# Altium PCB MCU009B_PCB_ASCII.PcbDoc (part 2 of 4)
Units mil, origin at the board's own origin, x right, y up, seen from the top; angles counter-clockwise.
Board outline 2657.23 x 2215.46 mil, 10 copper layers (Top Layer, Internal-Plane 2, Mid-Layer 3, Mid-Layer 4, Internal-Plane 5, Internal-Plane 6, Mid-Layer 7, Mid-Layer 8, Internal-Plane 9, Bottom Layer), stack 60.8 mil thick; 232 components, 196 nets, 851 pads, 493 vias.
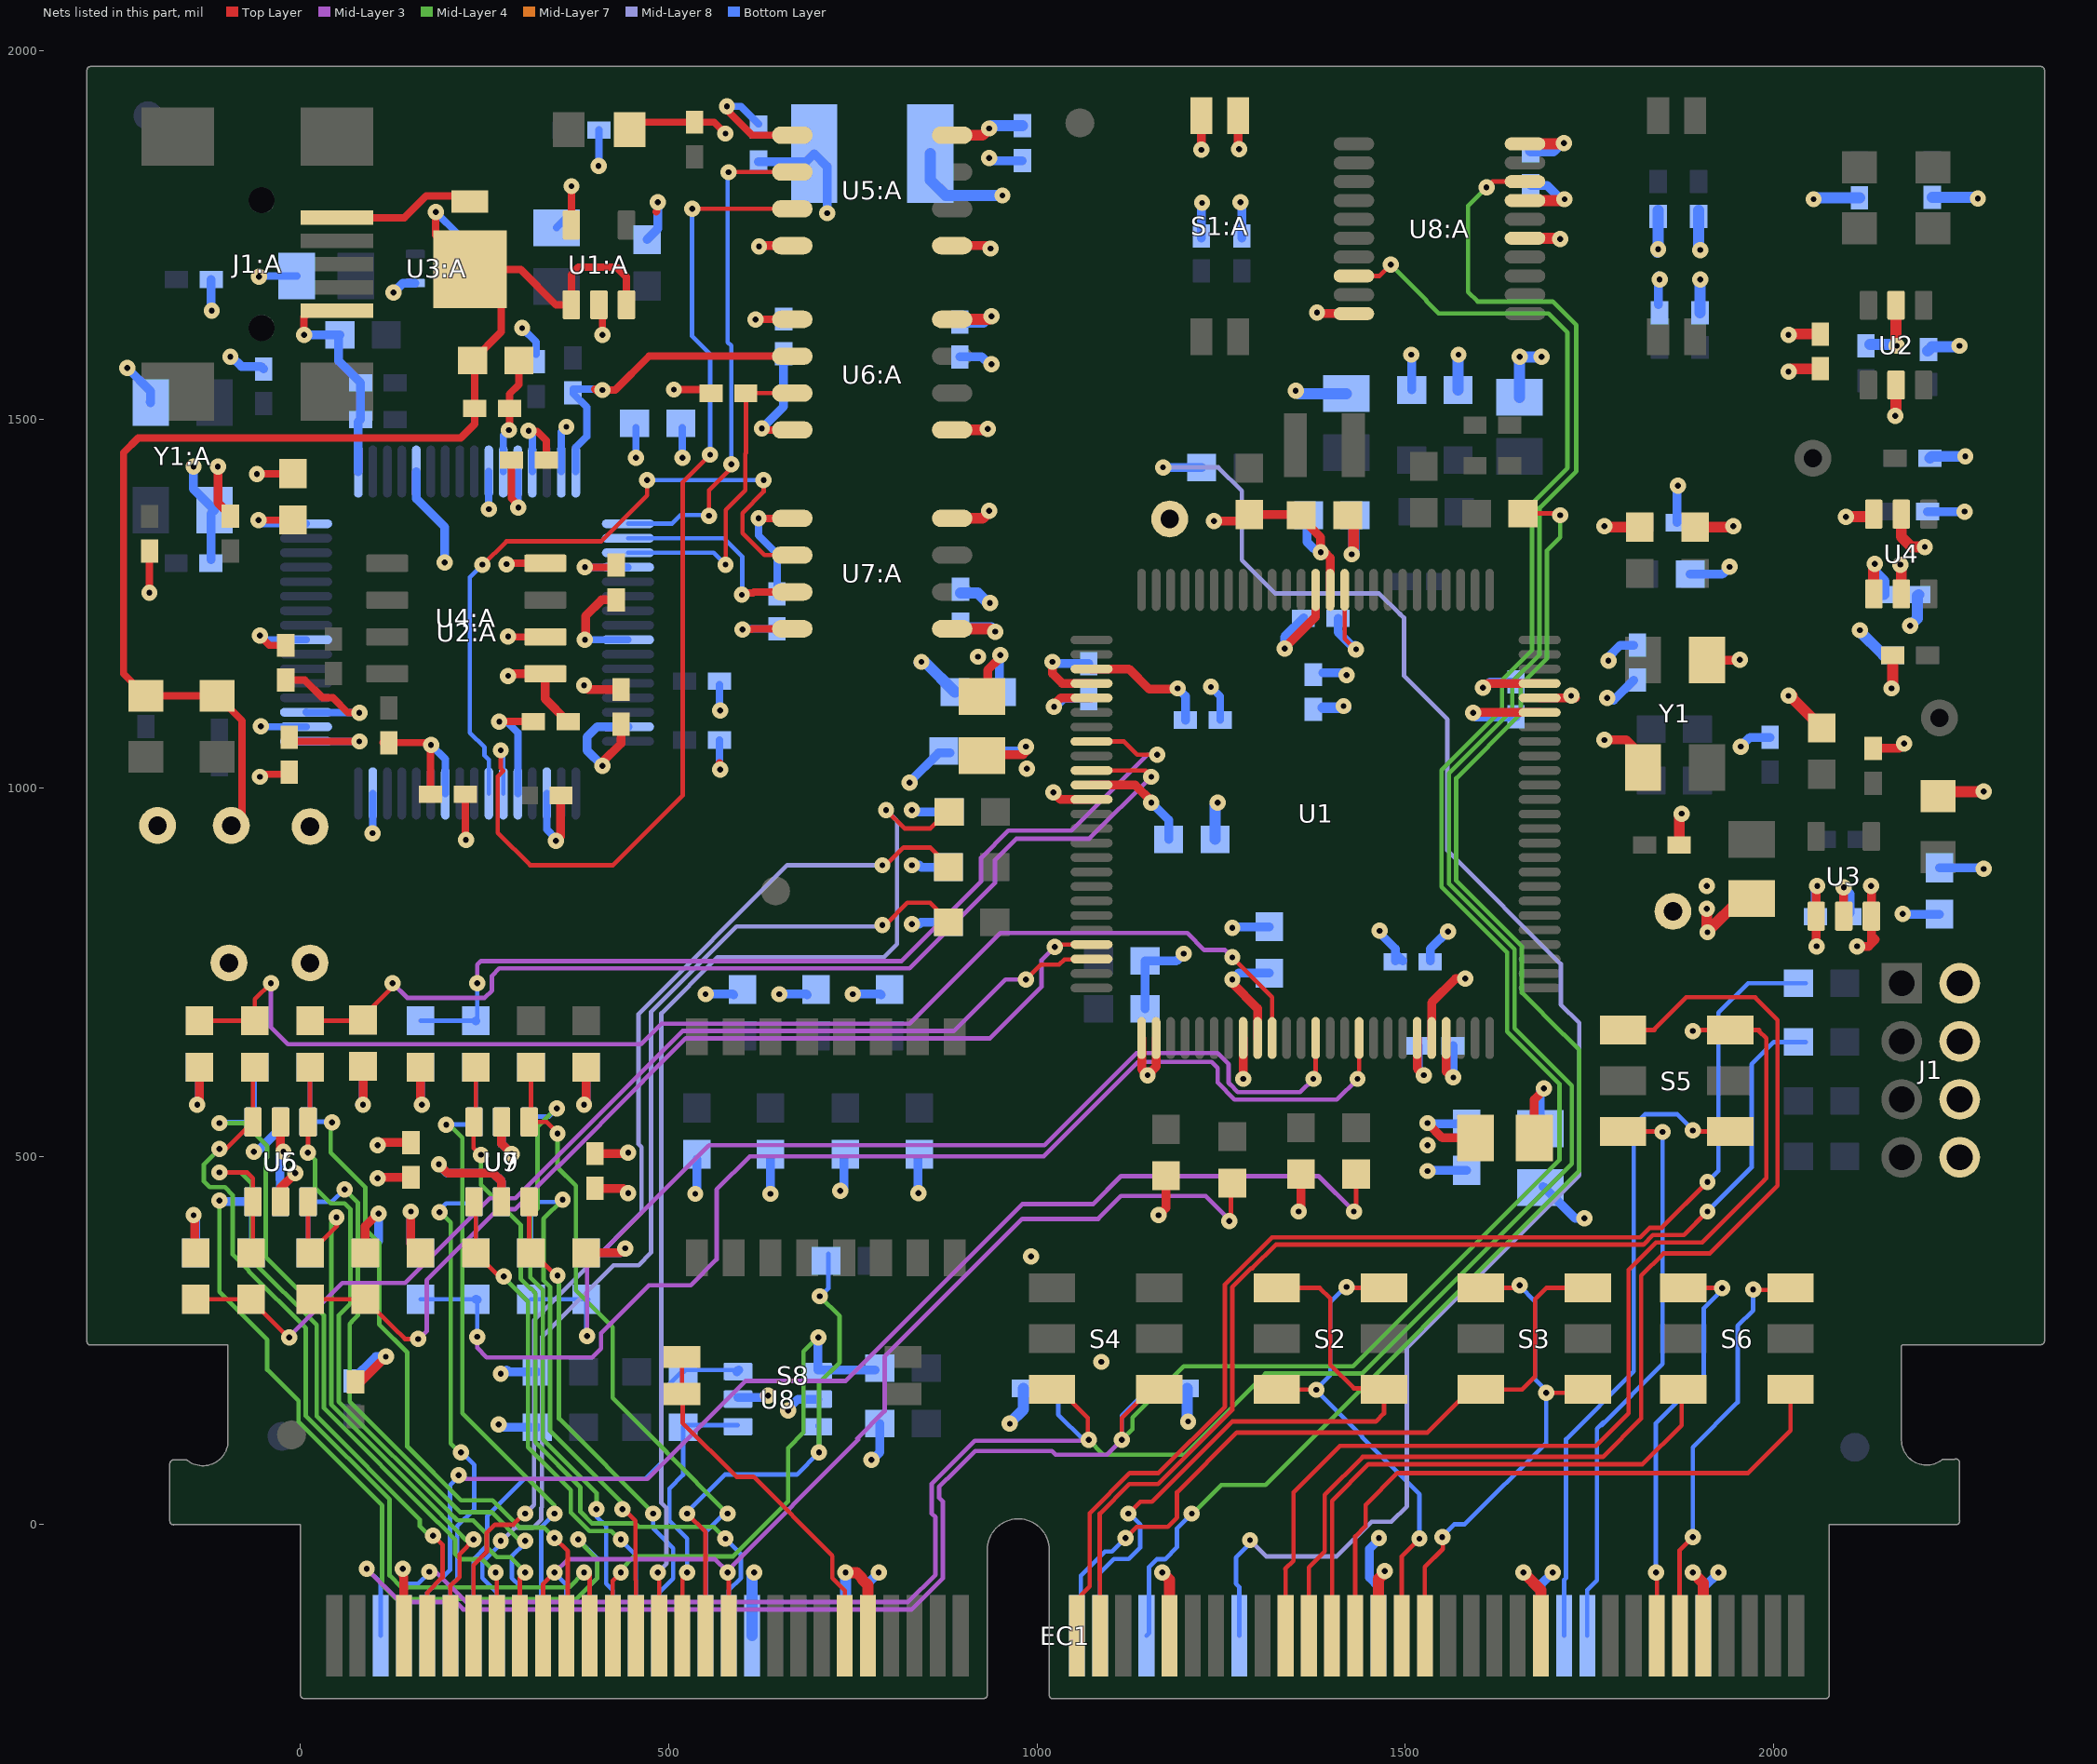
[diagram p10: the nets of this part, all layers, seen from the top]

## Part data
C1 C2 C8 C20 C21 C24 C27: library part CMP-0007318-5, "CAP, CERM, 10 uF, 10 V, +/- 20%, X5R, 0603"
C1:A C3 C4 C5 C6 C6:A C7:A C8:A C9 C9:A C10:A C11:A C12:A C14 C14:A C15 C16 C16:A C17 C18 C19:A C20:A C21:A C22:A C23:A C24:A C25 C25:A C31 C32 C33: library part CMP-0006629-2, "CAP, CERM, 0.1 uF, 10 V, +/- 10%, X7R, 0402"
C2:A C3:A C5:A C13:A C15:A: library part CMP-0007312-5, "CAP, CERM, 4.7 uF, 6.3 V, +/- 20%, X5R, 0603"
C4:A C26 C29 C30: library part CMP-0006639-2, "CAP, CERM, 0.01 uF, 16 V, +/- 10%, X7R, 0402"
C7: library part CMP-0008285-2, "CAP, CERM, 10 uF, 10 V, +/- 10%, X5R, 0805"
C10 C11 C12 C13 C19 C60 C61: library part CMP-0007323-5, "CAP, CERM, 2.2 uF, 10 V, +/- 10%, X5R, 0603"
C17:A C18:A: library part CMP-0006443-2, "CAP, CERM, 27 pF, 50 V, +/- 5%, C0G/NP0, 0402"
C22 C23: library part CMP-0006420-2, "CAP, CERM, 15 pF, 50 V, +/- 5%, C0G/NP0, 0402"
C26:A: library part CMP-0009297-2, "CAP, CERM, 0.01 uF, 1500 V, +/- 10%, X7R, 1812"
C28: library part CMP-0006638-2, "CAP, CERM, 1000 pF, 16 V, +/- 10%, X7R, 0402"
C34 C35 C36 C37 C38 C39 C40: library part CMP-0007209-4, "CAP, CERM, 330 pF, 50 V, +/- 5%, C0G/NP0, 0603"
C41 C42 C43 C44 C45 C46 C47 C48 C49 C50 C51 C52 C53 C54 C55 C56 C57 C58 C59: library part CMP-0007378-5, "CAP, CERM, 0.1 uF, 16 V, +/- 10%, X7R, 0603"
D1 D2:A: library part CMP-0002960-2, "LED, Bright Green, SMD"
D1:A: library part CMP-0028747-1, "Diode, Schottky, 10 V, 1 A, AEC-Q101, POWERMITE"
D2 D3: library part CMP-0002951-2, "LED, Red, SMD"
D3:A D4:A: library part CMP-0002959-2, "LED, Blue, SMD"
EC1: library part CMP-0003813-2, "C2000 controlCARD-120HSEC Edge Connector for Samtec HSEC8-160-01-L-DV-A-BL"
FID1 FID2 FID3 FID4 FID5 FID6: library part CMP-0077181-1, "Fiducial mark.  There is nothing to buy or mount."
J1: library part CMP-0055568-1, "Header, 2mm, 4x2, Tin, TH"
J1:A: library part CMP-0054809-1, "Connector, Receptacle, USB Mini B 2.0, SMT"
L1: library part CMP-0003363-1, "Ferrite Bead, 220 ohm @ 100 MHz, 2 A, 0805"
L1:A L2:A: library part CMP-0003398-1, "Ferrite Bead, 600 ohm @ 100 MHz, 0.5 A, 0805"
L2: library part CMP-0003306-1, "Ferrite Bead, 60 ohm @ 100 MHz, 3 A, 0805"
L3: library part CMP-0058752-1, "Inductor, Multilayer, Ferrite, 2.2 uH, 1.3 A, 0.08 ohm, SMD"
Logo1: library part CMP-0074838-1, "Texas Instrument Corporate Signature"
Logo2: library part CMP-0074769-1
Logo3: library part CMP-0074847-1, "FCC_disclaimer"
LOGO4: library part CMP-0074844-1
R1 R2: library part CMP-0026938-5, "RES, 4.7 k, 5%, 0.063 W, AEC-Q200 Grade 0, 0402"
R1:A R10 R11 R23: library part CMP-0026962-3, "RES, 680, 5%, 0.063 W, AEC-Q200 Grade 0, 0402"
R2:A R4:A R8 R9 R9:A R15:A R16:A: library part CMP-0026825-5, "RES, 10 k, 5%, 0.063 W, AEC-Q200 Grade 0, 0402"
R3 R4 R5 R6 R7 R16 R17 R18 R19 R21 R22 R28 R32 R35 R36 R37 R38 R39 R40 R41 R42 R43 R44 R45 R46 R47 R48 R49 R50 R51 R52 R53 R54 R55 R56 R57 R58 R59 R60 R61 R62 R63 R64: library part CMP-0025697-4, "RES, 0, 5%, 0.1 W, AEC-Q200 Grade 0, 0603"
R3:A R6:A R12:A R13:A R29: library part CMP-0026822-3, "RES, 0, 5%, 0.063 W, AEC-Q200 Grade 0, 0402"
R5:A R7:A R8:A R11:A: library part CMP-0026852-3, "RES, 1.0 k, 5%, 0.063 W, AEC-Q200 Grade 0, 0402"
R10:A R27 R30 R31 R33 R34: library part CMP-0026890-5, "RES, 2.2 k, 5%, 0.063 W, AEC-Q200 Grade 0, 0402"
R12 R13: library part CMP-0026826-2, "RES, 10 M, 5%, 0.063 W, AEC-Q200 Grade 0, 0402"
R14 R15 R20: library part CMP-0020442-3, "RES, 0, 5%, 0.125 W, AEC-Q200 Grade 0, 0805"
R14:A: library part CMP-0026834-3, "RES, 12 k, 5%, 0.063 W, AEC-Q200 Grade 0, 0402"
R24: library part CMP-0026129-2, "RES, 1.00, 1%, 0.063 W, AEC-Q200 Grade 0, 0402"
R25 R26: library part CMP-0026949-3, "RES, 56 k, 5%, 0.063 W, AEC-Q200 Grade 0, 0402"
S1 S1:A S8: library part CMP-0002230-1, "Switch, SPST, 2 Pos, 25mA, 24VDC, SMD"
S2 S3 S4: library part CMP-0002123-2, "SLIDE SWITCH DPDT  .1A, SMT"
S5 S6: library part CMP-0002233-1, "Switch, Dual SPDT,  2 Pos, 0.1A, 6VDC, SMD"
S7: library part CMP-0002229-1, "Switch, SPST, 8 Pos, 25mA, 24VDC, SMD"
TP1 TP1:A TP2 TP2:A TP3 TP3:A TP4 TP5 TP6: library part CMP-0078143-2, "TEST POINT.  No entry in BOM."
U1: library part CMP-0078352-1, "Piccolo Microcontroller, PZ0100A (LQFP-100)"
U1:A: library part CMP-0073823-1, "Low-Noise, High PSRR, RF 200-mA Low-Dropout Linear Regulators, DBV0005A (SOT-23-5)"
U2: library part CMP-0051789-2, "Dual Buffer/Driver with Open-Drain Output, DBV0006A, LARGE T&R"
U2:A: library part CMP-0004796-1, "Dual High Speed USB To Multipurpose UART/FIFO IC, LQFP-64"
U3: library part CMP-0036866-2, "Single Output Low Noise LDO, 400 mA, Fixed 3.3 V Output, 1.7 to 5.5 V Input, with Reverse Current Protection, 5-pin SOT-23 (DBV), -40 to 85 degC, Green (RoHS & no Sb/Br)"
U3:A: library part CMP-0043096-2, "Low-Capacitance + / - 15 kV ESD-Protection Array for High-Speed Data Interfaces, 2 Channels, -40 to +85 degC, 5-pin SOT (DRL), Green (RoHS & no Sb/Br)"
U4: library part CMP-0067340-2, "High-Accuracy, Fixed-Threshold OV/UV Monitor, DDC0006A (SOT-23-T-6)"
U4:A: library part CMP-0005261-2, "2K Microwire Compatible Serial EEPROM, SOIC-8"
U5 U6 U7 U8 U9: library part CMP-0066599-1, "Automotive Low-Capacitance 4-Channel +/-15-kV ESD Protection Array for High-Speed Data Interfaces, DBV0006A (SOT-23-6)"
U5:A U6:A U7:A: library part CMP-0029375-1, "25 Mbps Dual Channels, 2 / 0, Digital Isolator, 3.3 V / 5 V, -40 to +125 degC, 8-pin SOIC (D), Green (RoHS & no Sb/Br)"
U8:A: library part CMP-0047070-3, "Octal Buffer/Driver With 3-State OUtputs, PW0020A (TSSOP-20)"
Y1: library part CMP-0080365-1, "Crystal, 20 MHz, 25 ppm, 18, SMD"
Y1:A: library part CMP-0004646-3, "Crystal, 12 MHz, 20pF, SMD"
ZZ1: library part CMP-0077236-1
ZZ2: library part CMP-0077237-1
ZZ3: library part CMP-0077238-1

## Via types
v1: diameter 22, hole 8, Top Layer to Bottom Layer, 414 vias
v2: diameter 22, hole 8, Top Layer to Bottom Layer, tented both sides, 79 vias

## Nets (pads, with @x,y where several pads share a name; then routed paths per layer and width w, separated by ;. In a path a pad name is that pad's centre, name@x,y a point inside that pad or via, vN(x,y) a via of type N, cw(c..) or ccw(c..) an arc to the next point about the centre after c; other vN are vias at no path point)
3V3: C7.2 C9.1 C10.2 C19.2 C20:A.1 C22:A.1 C24:A.1 C25:A.2 C31.1 L1.1 L2.1 R1.1 R2.2 R8.2 R9.2 R10.1 R11.1 R12.2 R13.2 R14.1 R15:A.2 R16:A.2 R20.2 R25.1 R26.2 R27.2 R28.2 R30.2 R31.2 TP2.1 U2.5 U4.3 U4.4 U4.5 U5:A.8 U6:A.8 U7:A.1 U8:A.20 | length 1989.6
  Top Layer w12: R1.1@75,193.62 81.62,193.62 v1(116,228) v1@118,230 ; L2.1@933.1,1127.4 933.1,1160.1 v1@949,1176 ; L1.1@1675,525 1675,577 v1@1689,591
  Top Layer w15: U7:A.1@883.5,1215.87 936.13,1215.87 v1@938,1214 ; U6:A.8@883.5,1635.87 933.87,1635.87 v1(938,1640) ; U5:A.8@883.5,1885.87 925.87,1885.87 v1(935,1895) ; U8:A.20@1662.34,1874 1714,1874 v1(1715,1875) ; R31.2@1871.72,922.4 1871.72,961.72 v1(1875,965) ; R28.2@1893.1,1353.9 v1@1944,1353.9 ; v1(1909,836) 1909,806 v1@1910,805 ; v1(1910,804) v1@1910,805 ; v1@1944,1356 v1(1945,1355) ; v1@1945,1353.9 1945.9,1353.9 v1@1946,1354 ; R20.2@1970,850 1955,850 v1@1910,805 ; v1(2020,1615) 2021.02,1616.02 C9.1@2063.1,1616.02 ; v1(2098,1368) 2135,1368 U4.3@2135.7,1368.7 ; U4.4@2135.7,1263.27 2135.7,1302.7 2136,1303 v1@2137,1303 ; U4.3@2135.7,1371.53 U4.3@2135.7,1368.7 ; U4.3@2137,1370 U4.3@2135.7,1368.7 ; U2.5@2165.91,1655 2165.91,1603.09 v1@2167,1602 ; v1(2172,1303) 2173.1,1301.9 U4.5@2173.1,1263.27
  Bottom Layer w12: R2.2@70.2,195.28 70,195.47 102.53,228 v1(116,228) ; v1@949,1180 949,1144 946,1141 C10.2@949.6,1137.4 ; R15:A.2@1223.1,1746.02 1223.1,1748.02 1223.1,1793.1 v1(1224,1794) ; v1(1276,1795) 1278.1,1792.9 1278.1,1748.02 R16:A.2@1278.1,1746.02 ; C7.2@1683.1,537.4 1683.1,587.1 v1(1688,592)
  Bottom Layer w15: C22:A.1@895,1632.24 927.24,1632.24 935,1640 v1(938,1640) ; C24:A.1@896.22,1217.24 937.76,1217.24 v1(943,1212) ; v1(935,1895) 938.62,1898.62 C20:A.1@980,1898.62 ; v1@962,137 981.38,156.38 R8.2@981.38,185 ; R9.2@1203.62,185 1203.62,141.38 v1(1205,140) ; C19.2@1571.5,1540 1571.5,1587.5 v1(1572,1588) ; R14.1@1655,1530 v1(1655,1585) v1@1684,1585 ; C25:A.2@1670,1864.62 1700.62,1864.62 v1@1710,1874 ; v1@1842,1727 1843.1,1728.1 1843.1,1776.78 R25.1@1843.1,1783.78 ; R26.2@1898.1,1783.78 1898.1,1776.78 1898.1,1731.9 v1(1900,1730) ; v1(2054,1799) 2055.86,1800.86 R10.1@2116.34,1800.85 ; v1@2115,1214 2149,1180 R30.2@2161.38,1180 ; R12.2@2130.23,1601.79 2165.21,1601.79 v1(2167,1600) ; v1@2137,1303 2137,1293 2149.48,1280.52 C31.1@2149.48,1262.4 ; R13.2@2209,1593 2214.62,1598.62 2250.62,1598.62 v1(2252,1600) ; R27.2@2211.72,1447.4 2214.32,1450 v1(2260,1450) ; R11.1@2215.08,1801.37 2275.63,1801.37 v1(2277,1800)
  other v1: 963,137 1909,867 920,1178 950,1180 2117,1214 2137,1304 1685,1585 1843,1731
EMU_1V8: C5:A.2 C6:A.2 C7:A.2 C8:A.2 U2:A.12 U2:A.37 U2:A.49 U2:A.64 | length 609.2
  Top Layer w10: v2(-56.72,1363.35) C5:A.2@-19.8,1363.35 ; C7:A.2@-17.19,1065.68 -14.33,1062.82 62.58,1062.82 ; 7.72,1063.23 62.17,1063.23 62.58,1062.82 ; v2(80,1063) 62.77,1063 62.58,1062.82 ; v2(270,1090) C8:A.2@316.38,1090 ; C6:A.2@286.57,1444.84 286.57,1393.06 295.88,1383.75 v2(295.88,1380.55) v2@295.12,1381.31
  Bottom Layer w10: v2(-56.72,1363.35) -55.68,1364.38 -55.68,1361.68 -52.5,1358.5 U2:A.64@7.72,1358.5 ; U2:A.49@7.72,1063.23 79.77,1063.23 v2(80,1063) ; v2(270,1090) 280,1090 295.12,1074.88 U2:A.37@295.12,992.36 ; v2@295.12,1381.31 U2:A.12@295.12,1429.37
EMU_3V3: C2:A.1 C9:A.2 C10:A.2 C11:A.2 C12:A.2 C19:A.2 C21:A.2 C23:A.2 L1:A.2 L2:A.2 R1:A.1 R2:A.2 R4:A.2 R9:A.1 R11:A.1 TP2:A.1 U1:A.5 U2:A.20 U2:A.31 U2:A.42 U2:A.50 U2:A.56 U4:A.6 U4:A.8 U5:A.1 U6:A.1 U7:A.8 | length 1573.2
  Top Layer w10: v2(-55.01,1206.64) -41.83,1193.46 C10:A.2@-19.8,1193.46 ; R9:A.1@112.18,1061.44 174.32,1061.44 v2(177.31,1058.45) 176.73,1057.87 C12:A.2@176.73,991.34 ; v2@281.2,1304.84 U4:A.8@332.48,1304.84 ; v2@282.79,1204.84 U4:A.6@332.48,1204.84 ; v2(367.99,1816.64) 367.79,1816.44 U1:A.5@367.79,1763.98 U1:A.5@371.93,1759.84 ; v2(386.22,1299.45) C9:A.2@425.79,1299.45 ; v2(506.99,1540.64) 552.37,1540.64 R2:A.2@552.6,1540.87 ; v2@576.5,1922.5 613.13,1885.87 U5:A.1@668.94,1885.87 ; v2(600,1215) 612.6,1215 613.61,1216.02 ; v2@617.22,1635.87 U6:A.1@655.6,1635.87 ; v2(617.99,1635.64) 655.37,1635.64 U6:A.1@655.6,1635.87 ; U7:A.8@646.99,1216.02 613.61,1216.02 ; U6:A.1@655.99,1636.26 U6:A.1@655.6,1635.87 ; U7:A.8@668.94,1215.87 613.76,1215.87 613.61,1216.02 ; U6:A.1@668.94,1635.87 U6:A.1@655.6,1635.87
  Top Layer w12: v2(410,1030) 410,1035 435.2,1060.2 C11:A.2@435.2,1086.22
  Bottom Layer w10: v2(-56.01,1693.64) -54.8,1694.84 L2:A.2@-4.8,1694.84 ; v2@-55,1085 -52.91,1082.91 U2:A.50@7.72,1082.91 ; v2(-55.01,1206.64) -49.37,1201 U2:A.56@7.72,1201.02 ; v2@177.31,1058.26 196.69,1038.88 U2:A.42@196.69,992.36 ; v2(301.07,1624.04) 320.2,1604.91 R11:A.1@320.2,1588.46 ; L1:A.2@347.57,1760.29 367.99,1780.71 v2(367.99,1816.64) ; v2(386.22,1299.45) U2:A.20@444.72,1299.45 ; v2@405.09,1844.32 R1:A.1@405.09,1892.91 ; v2(518.49,1448.13) C2:A.1@518.49,1488.64 ; v2@568.82,1110.81 R4:A.2@568.82,1139.84 ; v2(579,1925) 598,1925 C19:A.2@622,1901 ; v2(600,1215) 601.02,1216.02 C23:A.2@646.99,1216.02 ; v2(617.99,1635.64) 618.61,1636.26 C21:A.2@655.99,1636.26
  Bottom Layer w12: v2(410,1030) 389.03,1050.97 389.03,1069.03 402.91,1082.91 U2:A.31@444.72,1082.91
  other v2: -53.73,1083.57 570,1105 281.99,1205.64 279.99,1303.64 404.72,1843.95
EMU_5V0: C1:A.2 C3:A.1 D1:A.1 D3:A.2 D4:A.2 TP1:A.1 U1:A.1 U1:A.3 U3:A.1 | length 1863.2
  Top Layer w10: TP1:A.1@-91,952 -79,964 -79,1090.97 D4:A.2@-113.01,1124.98 -209.63,1124.98 D3:A.2@-209.8,1124.8 -240,1155 -240,1455 -220.22,1474.78 217.5,1474.78 236.57,1493.86 C1:A.2@236.57,1514.84 236.57,1576.97 C3:A.1@233.7,1579.84 272.69,1618.83 D1:A.1@272.69,1703.05 ; v2(183.66,1781.59) 183.66,1750.38 D1:A.1@230.2,1703.84 ; D1:A.1@214.72,1724.53 251.2,1724.53 D1:A.1@272.69,1703.05 ; U1:A.3@442.6,1655.71 442.6,1693.38 429.37,1706.61 377.57,1706.61 367.79,1696.84 U1:A.1@367.79,1655.71 346.9,1655.71 299,1703.6 272.69,1703.6 D1:A.1@272.69,1703.05
  Bottom Layer w10: v2(183.66,1781.59) 214.72,1750.52 U3:A.1@214.72,1724.53
EMU_GND: C1:A.1 C2:A.2 C3:A.2 C4:A.1 C5:A.1 C6:A.1 C7:A.1 C8:A.1 C9:A.1 C10:A.1 C11:A.1 C12:A.1 C13:A.2 C14:A.1 C15:A.2 C16:A.1 C17:A.1 C18:A.1 C19:A.1 C21:A.1 C23:A.1 C26:A.2 D2:A.1 J1:A.5 R5:A.2 R6:A.2 R12:A.1 R13:A.1 R14:A.1 TP3:A.1 U1:A.2 U2:A.1 U2:A.5 U2:A.10 U2:A.11 U2:A.13 U2:A.15 U2:A.25 U2:A.35 U2:A.47 U2:A.51 U3:A.4 U4:A.5 U5:A.4 U6:A.4 U7:A.5 Y1:A.2 Y1:A.4 | length 3004.6
  Top Layer w10: v2(-205,1265) -205,1321.02 C17:A.1@-204.8,1321.22 ; v2(-59,1426) -20.14,1426 C5:A.1@-19.8,1426.34 ; v2@-46.76,1018.44 C7:A.1@-17.19,1018.44 ; C10:A.1@-19.8,1146.22 5.94,1146.22 29.9,1122.26 44.29,1122.26 64.55,1102 v2(80,1102) ; v2(5,1615) 5,1639.06 13.82,1647.87 J1:A.5@49.86,1647.87 ; v2@98.14,938.03 v2@98.27,938.15 ; C12:A.1@223.98,991.34 223.98,930.55 v2@224.87,929.65 ; v2(282.99,1485.64) 283.82,1486.46 C1:A.1@283.82,1514.84 283.82,1534.46 296.69,1547.34 C3:A.2@296.69,1579.84 ; v2(309.8,1484.54) 310.63,1483.71 321.47,1483.71 333.82,1471.37 C6:A.1@333.82,1444.84 ; R13:A.1@352,989.84 R13:A.1@352,991 ; U1:A.2@405.2,1655.71 410,1650.9 v2(410,1615) ; D2:A.1@445,1895 453.46,1903.46 C4:A.1@531.46,1903.46 ; 482.79,1781.74 483.55,1782.5 ; C4:A.1@535,1907 C4:A.1@531.46,1903.46 ; v2@568.82,1033.81 570,1032.63 v2(570,1025) ; v2(577,1888) 561.54,1903.46 C4:A.1@535.2,1903.46 C4:A.1@531.46,1903.46 ; v2(621.97,1365.87) U7:A.5@668.94,1365.87 ; v2(626.37,1487.85) 628.35,1485.87 U6:A.4@668.94,1485.87
  Top Layer w12: v1(-112,1436) -112,1387 R12:A.1@-95,1370 ; v1(282,1152) 284.84,1154.84 U4:A.5@332.48,1154.84 332.48,1120.52 C8:A.1@362,1091 ; v1(347,928) 353,934 R13:A.1@353,991 ; C8:A.1@363.62,1090 C8:A.1@363.62,1091 ; v2(385,1139) 390.54,1133.46 C11:A.1@435.2,1133.46 ; v2(386.22,1200.87) 387.08,1201.72 387.08,1233.2 408.99,1255.12 C9:A.1@428.7,1255.12 ; v2(622.61,1735.03) 623.44,1735.87 U5:A.4@668.94,1735.87
  Bottom Layer w10: U2:A.51@7.72,1102.6 8.31,1102 v2(80,1102) ; v2@98.27,938.15 U2:A.47@98.27,992.36 ; v2@255.75,1379.73 U2:A.10@255.75,1429.37 ; U2:A.11@275.43,1429.37 275.43,1478.08 v2(282.99,1485.64) ; v2(309.8,1484.54) 314.8,1479.54 U2:A.13@314.8,1429.37 ; U2:A.35@334.49,992.36 334.49,943.51 346,932 v1@346,927 ; U2:A.15@354.17,1429.37 354.17,1483.17 v2(361,1490) ; v2@386.22,1201.02 U2:A.25@444.72,1201.02 ; C2:A.2@455.5,1488.64 v2(455.5,1447.9) v2@455.95,1447.44 ; v2@568.82,1033.81 R5:A.2@568.82,1064.84 ; v2(621.97,1365.87) 621.97,1342.64 646.99,1317.61 C23:A.1@646.99,1263.26
  Bottom Layer w12: v2(-235,1570) -203.11,1538.11 Y1:A.2@-203.11,1522.68 Y1:A.2@-204.05,1523.61 ; v2(-145,1436) -145,1405.51 Y1:A.4@-116.5,1377.01 -121.18,1372.32 C14:A.1@-121.18,1309.84 ; R6:A.2@-121.18,1689.84 -121.18,1648.42 v2(-120.28,1647.52) ; v1(-95,1585) -93,1585 -80,1572 -53.38,1572 C18:A.1@-50,1568.62 ; v2(5,1615) 5.16,1614.84 C15:A.2@53.7,1614.84 51.93,1613.07 51.93,1579.49 C16:A.1@81.57,1549.84 R14:A.1@81.57,1499.84 78.58,1496.85 U2:A.1@78.58,1429.37 ; v2(126.39,1672.23) 139.31,1685.16 U3:A.4@155.67,1685.16 ; U2:A.5@157.32,1429.37 157.32,1392.68 196,1354 v2(196,1306) ; v1@346,927 v1(347,928) ; C13:A.2@470.54,1744.14 485,1758.6 v2(485,1795) ; C19:A.1@621.88,1849.74 686.35,1849.74 C26:A.2@697.48,1860.87 715,1843.35 v2(715,1780) ; v2(626.37,1487.85) 655.99,1517.48 C21:A.1@655.99,1589.02
  other v2: 224.68,929.27 97.99,938.5 -55,1015 256.06,1378.28
EMU_SCI-RX: U2:A.38 U5:A.3 | length 1443.1
  Top Layer w6: v2(272,1051) 272,1026.55 275.43,1023.12 267.93,1015.62 267.93,938.94 311.88,895 424.53,895 518.89,989.36 518.89,1414.86 v2(556.16,1452.13) ; v2(531.76,1785.87) U5:A.3@668.94,1785.87
  Bottom Layer w6: v2@272,1050 275.43,1046.57 U2:A.38@275.43,992.36 ; v2(531.76,1785.87) 531.76,1613.03 556.16,1588.63 v2(556.16,1452.13)
EMU_SCI-TX: U2:A.39 U7:A.6 | length 936.4
  Top Layer w6: v2@247,1302 279.64,1334.64 408.39,1334.64 470.5,1396.75 v2(470.5,1417.77) ; v2(628.8,1417.77) 628.8,1401.8 ; 629,1402 628.8,1401.8 ; U7:A.6@668.94,1315.87 629.88,1315.87 600,1345.74 600,1373 628.8,1401.8
  Bottom Layer w6: v2(247,1303) 230,1286 230,1075 250,1055 250,1044 255.75,1038.25 U2:A.39@255.75,992.36 ; v2@470.17,1418.09 v2(470.5,1417.77) v2(628.8,1417.77)
EMU_TCK: R3:A.1 U2:A.16 U6:A.2 | length 455.1
  Top Layer w10: v2@399.41,1541.22 400.63,1540 v2(410,1540) 427.35,1540 473.22,1585.87 U6:A.2@668.94,1585.87
  Bottom Layer w10: U2:A.16@373.86,1429.37 373.86,1462.11 388.79,1477.04 388.79,1516.75 370.2,1535.34 370.2,1541.22 408.78,1541.22 v2(410,1540)
EMU_TDI: U2:A.17 U5:A.2 | length 686.5
  Top Layer w6: v2(554.73,1369.33) 554.73,1404.05 588,1437.32 586.32,1439 v2(585,1439) ; v2@581.22,1835.87 U5:A.2@668.94,1835.87
  Bottom Layer w6: U2:A.17@444.72,1358.5 504.41,1358.5 516.1,1370.19 553.87,1370.19 v2(554.73,1369.33) ; v2@580,1835 580,1605 585,1600 v2(585,1439)
  other v2: 580.99,1835.64
EMU_TDO: U2:A.18 U7:A.7 | length 287.4
  Top Layer w10: v2(599.25,1262.09) 601.73,1264.58 614.42,1264.58 615.71,1265.87 U7:A.7@668.94,1265.87
  Bottom Layer w6: U2:A.18@444.72,1338.82 574.74,1338.82 599.9,1313.66 v2@599.9,1263.08
EMU_TMS: R2:A.1 U2:A.19 U6:A.3 | length 447.8
  Top Layer w6: v2@577.31,1302.67 577.31,1377.38 604,1404.07 604,1453.77 604.84,1454.61 604.84,1535.87 U6:A.3@668.94,1535.87
  Bottom Layer w6: U2:A.19@444.72,1319.13 560.95,1319.13 v2(577.12,1302.96)
EMU_USB_5V0: D1:A.2 J1:A.1 | length 195.6
  Top Layer w10: J1:A.1@49.86,1773.86 141.21,1773.86 170.65,1803.3 222.74,1803.3 D1:A.2@230.2,1795.84
GND: C1.2 C2.2 C3.1 C4.1 C5.1 C6.1 C7.1 C8.2 C9.2 C10.1 C11.1 C12.1 C13.1 C14.2 C15.2 C16.2 C17.2 C19.1 C20:A.2 C22.2 C22:A.2 C23.2 C24.2 C24:A.2 C25.2 C25:A.1 C26.1 C26:A.1 C27.1 C29.1 C30.1 C31.2 C32.2 C33.2 C34.1 C35.1 C36.1 C37.1 C38.1 C39.1 C40.1 C41.1 C42.1 C43.1 C44.1 C45.1 C46.1 C47.1 C48.2 C49.2 C50.2 C51.2 C52.2 C53.2 C54.2 C55.2 C56.2 C57.2 C58.2 C59.2 C60.1 C61.1 D1.1 EC1.7 EC1.38 EC1.46 EC1.47 EC1.65 EC1.83 EC1.97 EC1.111 J1.2 J1.4 J1.6 J1.8 R15.1 R17.1 R32.2 R33.2 R34.1 R55.1 R56.1 R57.1 R58.1 R59.1 S1:A.3 S1:A.4 TP4.1 U1.5 U1.12 U1.26 U1.27 U1.33 U1.45 U1.72 U1.86 U2.2 U3.2 U4.2 U5.2 U5:A.5 U6.2 U6:A.5 U7.2 U7:A.4 U8.2 U8:A.10 U8:A.15 U8:A.17 U9.2 Y1.2 Y1.4 | length 6197.3
  Top Layer w6: U1.86@1417.47,1268.7 1417.47,1202.53 v1@1432.5,1187.5
  Top Layer w12: v1(-145,420) -143.1,418.1 C48.2@-143.1,369.1 ; v1(-140,570) -136.9,573.1 C51.2@-136.9,620.9 ; U5.2@-26.9,438.27 -26.9,457.1 v1(-7,477) v1@-6,476 ; v1(85,570) C50.2@85,622.01 ; C49.2@88.1,368.9 C49.2@88.1,371.9 ; C49.2@90,370 C49.2@88.1,371.9 ; v1@101,468 104.38,471.38 C32.2@150,471.38 ; v1@107,424 88.1,405.1 C49.2@88.1,371.9 ; v1(139,-60) 139,-69 140.55,-70.55 EC1.7@140.55,-150.67 ; v1(150,425) 150,381 C56.2@161,370 ; C59.2@163.1,620.9 163.1,576.9 v1@170,570 ; v1(188,489) 200,477 262,477 273.1,465.9 U9.2@273.1,438.27 ; v1(385,570) 388.1,573.1 C58.2@388.1,620.9 ; C57.2@388.1,368.9 434.9,368.9 v1(441,375) ; C33.2@400,456.38 438.62,456.38 v1(445,450) ; U5:A.5@883.5,1735.87 933.13,1735.87 v1(937,1732) ; v1(1022,994) 1031.75,984.25 U1.12@1073.97,984.25 ; v1(1023,1110) 1023,1113 1032.04,1122.04 U1.5@1073.97,1122.04 ; U1.26@1141.88,660.43 1141.88,618.12 v1(1150,610) 1161.56,621.56 U1.27@1161.56,660.43 ; v1(1165,420) 1175,430 R58.1@1175,473.5 ; v1(1223,1866) 1223.1,1866.1 S1:A.4@1223.1,1912.4 ; S1:A.3@1273.1,1912.4 1273.1,1867.9 v1(1274,1867) ; U1.33@1279.67,660.43 1279.67,605.33 v1(1280,605) ; v1(1355,425) 1358.1,428.1 R59.1@1358.1,475.9 ; v1(1380,1645) 1381.32,1643.68 U8:A.10@1430.05,1643.68 ; U1.45@1515.9,660.43 1515.9,619.1 v1(1525,610) ; v1@1611.73,1141.73 U1.72@1682.23,1141.73 ; v1(1770,1065) 1800,1065 1821.52,1043.48 Y1.4@1821.52,1027.83 ; v1(1770,1355) 1771.1,1353.9 v1@1776.1,1353.9 ; v1@1775,1172 v1(1775.5,1172.5) ; Y1.2@1908.13,1173.5 1953.5,1173.5 v1(1954,1174) ; U3.2@2095,825.87 v1(2095,865) ; C26.1@2135,1053.62 2170.62,1053.62 v1(2177,1060)
  Top Layer w15: v1(740,-65) 755,-65 762.5,-72.5 762.5,-74.32 770.47,-82.29 EC1.47@770.47,-150.67 ; U7:A.4@883.5,1365.87 925.87,1365.87 935,1375 v1(935,1376) ; U6:A.5@883.5,1485.87 931.87,1485.87 v1(933,1487) ; v1(1170,-65) 1179.92,-74.92 EC1.65@1179.92,-150.67 ; v1@1429.6,1325.6 C2.2@1429.6,1357.4 ; EC1.83@1463.38,-150.67 1463.38,-73.62 v1@1473,-64 ; v1(1660,-65) 1683.86,-88.86 EC1.97@1683.86,-150.67 ; U8:A.15@1662.34,1746.05 v1@1708.95,1746.05 ; U8:A.17@1662.34,1797.23 1714.23,1797.23 v1(1716,1799) ; v1@1776.1,1353.9 R32.2@1818.1,1353.9 ; v1(1890,-65) 1904.33,-79.33 EC1.111@1904.33,-150.67 ; v1(2020,1565) 2023.78,1568.78 C9.2@2063.1,1568.78 ; v1@2025,1125 2025,1121.5 C27.1@2065,1081.5 ; v1@2159.48,1135.52 v1(2160,1135) 2161.38,1136.38 C30.1@2161.38,1180 ; v1(2165,1505) 2165.91,1505.91 U2.2@2165.91,1546.73 ; U4.2@2173.1,1371.53 2173.1,1340.9 2187,1327 v1(2205,1327) ; D1.1@2223.1,988.74 2229.36,995 v1(2285,995)
  Bottom Layer w6: v1@1955,1055 v1@1955.5,1055.5
  Bottom Layer w10: v1(1236,1137) 1248.62,1124.38 C14.2@1248.62,1092
  Bottom Layer w12: v1(-145,420) -141.9,416.9 C44.1@-141.9,368.9 ; v1(-140,570) -136.9,573.1 C41.1@-136.9,620.9 ; v1(-63,506) -60.37,506 v1@-59.69,506.69 ; v1@-59,506 -26.9,538.1 U6.2@-26.9,546.53 ; v1@80,570 v1@85,575 ; v1(85,570) v1@85,575 ; C42.1@85,622.01 v1@85,575 ; C43.1@89,368 106,385 v1(106,422) ; v1(150,425) 150,382 C53.2@166,366 ; C54.2@163.1,620.9 163.1,571.9 v1(165,570) ; v1@186,490 199,477 262,477 273.1,465.9 U7.2@273.1,438.27 ; v1(269,136) 272.6,132.4 C46.1@321.6,132.4 ; v1(272,205) 275,205 280,210 282.6,207.4 C47.1@321.6,207.4 ; v1(385,570) 388.1,573.1 C55.2@388.1,620.9 ; C52.2@388.1,368.9 433.9,368.9 v1@441,376 ; v1(536,449) 538.1,451.1 C34.1@538.1,495.9 ; v1(550,720) 587,720 C35.1@588.1,718.9 ; v1(638,449) 638.1,449.1 C36.1@638.1,495.9 ; v1(650,720) 687,720 C37.1@688.1,718.9 ; v1@660,155 675.4,170.4 U8.2@702.23,170.4 ; v1(733,453) 734.2,453 738.1,456.9 C38.1@738.1,495.9 ; v1(750,720) 787,720 C39.1@788.1,718.9 ; v1(775,88) 776.21,88 786.6,98.4 C45.1@786.6,137.4 ; v1(827,1007) 827,1008 866.4,1047.4 C11.1@881.6,1047.4 ; v1(830,815) 840,815 842.4,817.4 R56.1@881.6,817.4 ; v1(830,895) 840,895 842.6,892.4 880.6,892.4 R55.1@881.6,892.4 ; v1(830,970) 832.6,967.4 R57.1@881.6,967.4 ; C40.1@838.1,495.9 838.1,450.9 v1(839,450) ; v1@843,1170 v1(843,1171) ; C22:A.2@895,1585 925,1585 935,1575 v1(938,1575) ; v1(935,1855) 938.62,1851.38 C20:A.2@980,1851.38 ; v1(1023,1110) 1025,1110 1036.38,1121.38 C6.1@1070,1121.38 ; C60.1@1146.5,700 C61.1@1146.5,765 1189,765 v1(1199,775) v1@1200,776 ; v1(1265,810) 1266.5,811.5 C13.1@1315,811.5 ; C17.2@1408.62,1230 1408.62,1211.38 v1@1430,1190 ; v1@1463,805 1486.38,781.62 C5.1@1486.38,775 ; v1@1465,805 v1(1465,806) ; C5.1@1486.38,765 C5.1@1486.38,775 ; C5.1@1496.38,765 C5.1@1486.38,775 ; v1(1508,1588) 1508.5,1587.5 C19.1@1508.5,1540 ; C15.2@1517.27,649.99 1517.27,617.73 v1(1525,610) ; v1(1530,480) 1530.9,480.9 C8.2@1583.1,480.9 ; v1@1607,1136 1614.62,1143.62 C16.2@1650,1143.62 ; C25:A.1@1670,1817.38 1692.62,1817.38 1711,1799 v1(1716,1799) ; C7.1@1687,459 1730,416 v1(1743,416) ; v1(1775.5,1172.5) 1775.5,1177.5 1791.62,1193.62 C4.1@1810,1193.62 ; R33.2@1843.1,1656.02 1843.1,1694.9 1845,1693 v1(1845,1690) ; C23.2@1868.62,1360 1868.62,1408.62 v1(1870,1410) ; R17.1@1886.5,1290 1930,1290 v1(1940,1300) ; v1(1955,1056) 1967.62,1068.62 C22.2@1995,1068.62 ; v1(2095,865) 2103.62,856.38 C25.2@2103.62,830 ; C29.1@2208.62,1375 2258,1375 v1@2260,1377 ; C24.2@2225,891.5 2283.5,891.5 v1(2285,890)
  Bottom Layer w15: EC1.38@612.99,-150.67 612.99,-67.01 615,-65 v1(616,-65) ; EC1.46@738.98,-150.67 740,-149.64 v1(740,-65) ; v1@840,1170 843,1170 848.5,1170 C10.1@888.5,1130 ; C26:A.1@854.96,1860.87 854.96,1825.04 876,1804 v1(953,1804) ; C24:A.2@896.22,1264.49 919.51,1264.49 933,1251 v1(936,1251) ; C12.1@1241.5,930 1241.5,976.5 v1(1245,980) ; v1(1351,1539) 1352,1539 1356,1535 R15.1@1420,1535 ; 1388.1,1108.78 1418.78,1108.78 1419,1109 1417,1111 v1(1416,1111) ; v1@1428,1317 1430,1319 C1.2@1430,1362 ; v1@1430,1190 1431,1190 v1(1433,1188) ; v1@1432,1192 v1@1434,1190 ; R34.1@1900,1645 v1(1900,1690) ; v1(2185,1220) 2195,1230 2195,1260.68 C31.2@2196.72,1262.4
  other v1: 1472,-63 662,155 1087,221 992,364 105,470 2020,1125 1605,1136 1427,1317 2259,1375 1710,1745
HSEC_5V0: C24.1 C25.1 EC1.48 EC1.84 EC1.98 EC1.112 TP1.1 U3.1 U3.3 | length 704.1
  Top Layer w12: v1@2058,789 2057.6,789.4 U3.1@2057.6,825.87 2057.6,867.6 2058.2,867 v1(2059,867) ; v1(2113,785) 2128.8,785 2137.8,794 2135.8,796 2132.4,792.6 U3.3@2132.4,825.87 2132.4,865.6 v1@2131,867
  Bottom Layer w12: EC1.48@770.47,-150.67 770.47,-79.53 v1(785,-65) ; EC1.84@1463.38,-150.67 1463.38,-84.08 1451,-71.7 1451,-33 1464,-20 v1(1464,-18) ; EC1.98@1683.86,-150.67 1683.86,-81.14 v1(1700,-65) ; EC1.112@1904.33,-150.67 1904.33,-85.67 v1(1925,-65) ; C25.1@2056.38,830 2056.38,866.38 2057.76,865 2059,866.24 v1(2059,867) ; v1(2175,829) 2175.5,828.5 C24.1@2225,828.5
  other v1: 2058,785 2132,867
HSEC_ADC-A0,B15,C15,DACA: EC1.9 R36.2 U5.1 | length 940.1
  Top Layer w6: v1(-110,478) -72,478 -64.3,470.3 U5.1@-64.3,438.27 -64.3,380.1 -60,375.8 R36.2@-66.9,368.9 ; EC1.9@172.05,-150.67 172.05,-92.41 193,-71.46 193,-27 v1@179,-13
  Mid-Layer 4 w6: v1(-110,478) -81,478 -66,463 -66,359 22,271 22,147.14 162,7.14 162,-2 175,-15 v1(180,-15)
HSEC_ADC-A1,DACB: EC1.11 R38.2 U5.3 | length 802.9
  Top Layer w6: R38.2@10,370 10.5,370.5 U5.3@10.5,438.27 ; R38.2@13.1,368.9 50,405.8 49,406.8 v1(49,417) ; EC1.11@203.54,-150.67 203.54,-83.46 216,-71 216,-40 v1@237,-19
  Mid-Layer 4 w6: v1@50,418 v1(49,417) 42,410 42,163 191.6,13.4 191.6,13 213,-8.4 213,-8.88 225.12,-21 v1@232,-21
  other v1: 235,-20
HSEC_ADC-A2,B6,PGA1_IN: EC1.15 R37.1 U6.1 | length 1010.5
  Top Layer w6: v1(265,-65) 266.53,-66.53 EC1.15@266.53,-150.67
  Mid-Layer 4 w6: v1(-110,545) -76.54,545 -45,513.46 -45,498.54 -47,496.54 -47,363 32,284 32,157.98 186.98,3 187.46,3 203,-12.54 203,-13.02 210,-20.02 210,-39.46 217.54,-47 247,-47 v1(265,-65)
  Bottom Layer w6: v1(-110,545) -108.47,546.53 U6.1@-64.3,546.53 ; U6.1@-64,548 -61.9,550.1 R37.1@-61.9,620.9
HSEC_ADC-A3: EC1.17 R41.2 U5.4 | length 946.5
  Top Layer w6: v1(10,505) 10.5,505.5 U5.4@10.5,546.53 ; U5.4@13.1,545.1 R41.2@13.1,620.9 ; EC1.17@298.03,-150.67 298.03,-71.97 v1(305,-65)
  Mid-Layer 4 w6: v1(10,505) 20,495 20,457 41,436 60,436 68,428 68,300 52,284 52,167.14 201.6,17.54 201.6,17.4 213.23,5.77 234.68,5.77 253,-12.54 253,-30.46 266.54,-44 285,-44 v1@306,-65
HSEC_ADC-A4,B8,PGA2_IN: EC1.21 R39.1 U6.3 | length 991.5
  Top Layer w6: v1(345,-18) 363,-36 363,-148.69 EC1.21@361.02,-150.67
  Mid-Layer 4 w6: v1@41,545 41,505 88,458 88,401.54 107,382.54 107,272 145,234 145,106 218,33 261,33 297,-3 ; 297,-4 331,-4 v1(345,-18)
  Bottom Layer w6: R39.1@13.1,620.9 13.1,616.1 13.1,550.1 10,547 v1@42,547
  Bottom Layer w12: R39.1@10.5,613.5 13.1,616.1 15,618 R39.1@15,622
  other v1: 43,546
HSEC_ADC-A5: EC1.23 R44.2 U5.6 | length 1200.6
  Top Layer w6: v1@-109,510 -100.84,510 U5.6@-64.3,546.53 R44.2@-64.3,616.3 ; EC1.23@392.52,-150.67 v1@392.52,-67.48
  Top Layer w12: R44.2@-67,620 -67,619 R44.2@-64.3,616.3
  Mid-Layer 4 w6: v1(-110,510) -131,489 -131,466 -123,458 -102.54,458 -92,447.46 -92,367 -70,345 -70,344 7.36,266.64 7.36,147.64 121,34 121,-69 137,-85 365,-85 v1(385,-65)
HSEC_ADC-A6,PGA5_IN: EC1.25 R43.1 U8.1 | length 723.5
  Top Layer w6: EC1.25@424.01,-150.67 424.01,-75.99 v1(435,-65)
  Mid-Layer 4 w6: v1(435,-65) 435,-61 453,-43 587.46,-43 662,31.54 662,104 683,125 683,235 702,254 v1(703,254)
  Bottom Layer w12: v1(703,254) 702.23,254.77 702.23,209.8 702.43,210 R43.1@780,210
HSEC_ADC-A8,PGA6_OF: EC1.33 R35.1 U8.3 | length 727.7
  Top Layer w6: v1(525,15) 550,-10 EC1.33@550,-150.67
  Mid-Layer 4 w6: v1(704,98) 704,192 732,220 732,283 v1(705,310)
  Bottom Layer w6: v1(525,15) 525,17 576,68 674,68 v1(704,98) ; v1@702,102 v1@703,103 ; U8.3@702.23,135 U8.3@702.23,133 704,131.23 v1(704,98) ; v1@705,99 v1(704,98) ; v1@706,310 716.6,320.6 R35.1@716.6,367.4
HSEC_ADC-A9: EC1.27 R47.2 U7.1 | length 770.8
  Top Layer w6: v1@438,22 455,5 455,-75 455.51,-75.51 EC1.27@455.51,-150.67
  Mid-Layer 4 w6: v1(356,441) 330,415 330,331.54 339,322.54 339,127 437,29 v1(437,21)
  Bottom Layer w6: U7.1@312.2,438 313.1,438.9 U7.1@313.1,438 ; R47.2@313.1,368.9 U7.1@313.1,438 ; v1@356,442 352,438 U7.1@313.1,438
HSEC_ADC-B0: EC1.12 R49.2 U7.3 | length 740
  Mid-Layer 4 w6: v1@190,424 204,410 204,110 v1@220,94 ; v1(218,98) v1@220,98
  Bottom Layer w6: v1@188,426 198,436 230,436 232.9,438.9 238.1,438.9 R49.2@238.1,368.9 ; EC1.12@203.54,-150.67 203.54,-83.46 213,-74 213,-2 236,21 236,81 219,98 v1(218,98)
  other v1: 189,424
HSEC_ADC-B1,A10,C10,PGA7_IN: EC1.14 R46.1 U8.6 | length 656.4
  Bottom Layer w6: 235,-47 235.04,-46.96 ; EC1.14@235.04,-150.67 235.04,-46.96 ; R46.1@520,207 522.8,209.8 U8.6@593.97,209.8 ; R46.1@520,210 490,180 490,84 468,62 304,62 253.5,11.5 253.5,-28.5 235.04,-46.96
  Bottom Layer w12: EC1.14@235.04,-150.67 EC1.14@237,-148.71 ; U8.6@592.4,207.4 U8.6@595,210
HSEC_ADC-B2,C6,PGA3_IN: EC1.18 R40.1 U6.4 | length 892
  Mid-Layer 4 w6: v1(60,455) 78,437 78,284 69,275 ; 69.27,274.73 67,272.46 67,167 217,17 259.4,17 301.4,-25 304.4,-22 v1(305,-22)
  Bottom Layer w6: R40.1@10,370 10.5,370.5 10.5,374.5 U6.4@10.5,438.27 43.27,438.27 v1(60,455) v1@61,456 ; EC1.18@298.03,-150.67 298.03,-83.49 287,-72.46 287,-43 305,-25 v1(305,-22)
  Bottom Layer w12: R40.1@10.5,374.5 R40.1@15,370
HSEC_ADC-B3,VDAC: EC1.20 R53.2 U7.4 | length 868.7
  Mid-Layer 4 w6: v1(198,543) 202,543 220,525 220,151.14 345,26.14 v1(345,15)
  Bottom Layer w6: v1@208,543 230,543 238.1,551.1 R53.2@238.1,620.9 ; EC1.20@329.53,-150.67 327,-148.14 327,-3 v1(345,15)
HSEC_ADC-B4,C8,C3,PGA4_IN: EC1.24 R42.1 U6.6 | length 1253.8
  Mid-Layer 3 w6: v1@377,-23 v1(377,-20)
  Mid-Layer 4 w6: v1(-110,440) -110,316 -45,251 -45,210.36 -2.64,168 -2.64,139.64 111,26 111,-82 130,-101 374.46,-101 403,-72.46 403,-47 v1@377,-21
  Bottom Layer w6: U6.6@-69.27,438.27 -66,435 -66.9,434.1 R42.1@-66.9,368.9 ; v1(377,-20) 403,-46 403,-72.46 392.52,-82.94 EC1.24@392.52,-150.67
  Bottom Layer w12: v1(-110,440) -108.27,438.27 -69.27,438.27 U6.6@-64.3,438.27
HSEC_ADC-C0: EC1.26 R60.2 U7.6 | length 893.5
  Mid-Layer 4 w6: v1@348,566 322,540 322,429 312,419 312,335.4 329,318.4 329,116 402,43 v1(402,21)
  Bottom Layer w6: U7.6@310.5,546.53 U7.6@312.48,548.52 ; R60.2@313.1,611.1 313.1,552.1 311,550 U7.6@312.48,548.52 ; v1@348,564 338,554 317.97,554 U7.6@312.48,548.52 ; v1(402,21) 402,11 415,-2 415,-80 424.01,-89.01 EC1.26@424.01,-150.67
  Bottom Layer w12: R60.2@313.1,611.1 315,613 R60.2@315,617
  other v1: 348,565
HSEC_ADC-C1: EC1.28 R61.2 U9.1 | length 710.6
  Top Layer w6: U9.1@235,439.8 238.1,442.9 R61.2@238.1,368.9 270,337 v1(276,337)
  Top Layer w12: R61.2@235,370 R61.2@235.7,370.7
  Mid-Layer 4 w6: v1@275.5,336.5 309,303 309,105 367,47 367,16.4 392.2,-8.8 421.8,-8.8 v1@434,-21
  Bottom Layer w6: v1@434,-20 455.51,-41.51 EC1.28@455.51,-150.67
  other v1: 435,-20
HSEC_ADC-C2: EC1.30 R62.2 U9.3 | length 673.6
  Top Layer w6: R62.2@310.5,371.5 U9.3@310.5,438.27 ; R62.2@313.1,368.9 316.11,368.89 v1@347,338 ; v1(349,338) v1@349,340
  Mid-Layer 4 w6: v1@351,334 351,144 480,15 v1(479,15)
  Bottom Layer w6: v1(479,15) 479,-5 506,-32 506,-73 487.01,-91.99 EC1.30@487.01,-150.67
HSEC_ADC-C4: EC1.34 R63.2 U9.4 | length 915.8
  Top Layer w6: U9.4@310.5,543.5 U9.4@310.5,546.53 U9.4@313.1,546.53 ; R63.2@313.1,620.9 U9.4@313.1,546.53 ; v1@350,531 334.47,546.53 U9.4@313.1,546.53
  Mid-Layer 4 w6: v1(349,531) 349,485 374,460 374,318 424,268 424,172 497,99 ; 496.5,98.5 v1(580,15)
  Bottom Layer w6: EC1.34@550,-150.67 551,-149.67 551,-9 575,15 v1(580,15)
HSEC_ADC-C5,PGA6_IN: EC1.31 R45.1 U8.4 | length 382.2
  Top Layer w6: EC1.31@518.5,-150.67 518.5,-71.5 v1(525,-65)
  Mid-Layer 3 w6: v1@524,-64 v1(525,-65)
  Bottom Layer w6: R45.1@519.6,132.4 519.6,67.6 501,49 501,5 525,-19 v1@525,-64 ; R45.1@521,134 522,135 U8.4@593.97,135 ; v1(525,-65) v1@530,-65
HSEC_ADC-C14: EC1.36 R64.2 U9.6 | length 1025.8
  Top Layer w6: R64.2@238.1,620.9 238.1,548.1 235,545 235,511 v1@241,505
  Mid-Layer 4 w6: v1(245,502) 245,461 299,407 299,334 313,320 ; 313.13,320.13 319,314.26 319,111.86 380,50.86 380,17.54 395.77,1.77 454.23,1.77 459,-3 561,-3 v1(577,-19) ; v1@574.5,-21.5 v1@579,-26
  Bottom Layer w6: v1(577,-19) 598,-40 598,-72.46 581.49,-88.96 EC1.36@581.49,-150.67
HSEC_ADCVREFHI-EXT: EC1.45 S8.1 S8.2 | length 481.1
  Top Layer w6: S8.1@518.1,227.4 518.1,178.1 518.9,178.1 518.9,138.1 592,65 615,65 721,-41 ; 722,-43 722,-72.46 738.98,-89.43 EC1.45@738.98,-150.67
HSEC_GPIO-12: EC1.57 R3.1 | length 1640.8
  Top Layer w6: EC1.57@1059.39,-124 1059.39,-96 1071.5,-83.89 1071.5,15.5 1072,16 ; 1074,18 1072,16 ; v1(1910,465) 1848,403 1831.72,403 1818.72,390 1318.75,390 1255,326.25 1255,160 1165,70 1125.86,70 1072,16.14 1072,16
  Bottom Layer w6: v1(1910,465) 1925,480 1925,695 1965,735 R3.1@2033.5,735 R3.1@2043.5,735
HSEC_GPIO-13: EC1.59 R4.1 | length 1569.1
  Top Layer w6: EC1.59@1085.43,-150.67 1085.43,-75 1085,-75 1085,15 1125,55 1164.14,55 1265,155.86 1265,322.11 1290.87,347.98 1292.12,347.98 1324.14,380 1822.86,380 1835.86,393 1878,393 v1(1910,425)
  Bottom Layer w6: v1(1910,425) 1970,485 1970,625 2000,655 R4.1@2033.5,655 R4.1@2043.5,655
HSEC_GPIO-22: EC1.72 R19.2 | length 2313.5
  Mid-Layer 8 w6: v1(1171,1435) 1246,1435 1278,1403 1278,1309 1323,1264 1464,1264 1492.5,1235.5 ; v1(1289,-21) 1292.54,-21 1290.77,-22.77 1311,-43 1407,-43 1454,4 1481,4 1502,25 1502,239.98 1736,473.98 1736,681 1711,706 1711,761 1557,915 1557,1093.14 1498,1152.14 1498,1231 1493,1236
  Bottom Layer w6: EC1.72@1274.41,-150.67 1274.41,-84.41 1270,-80 1270,-45 1289,-26 v1(1289,-21)
  Bottom Layer w12: v1(1171,1435) R19.2@1223.5,1435
HSEC_GPIO-23: EC1.64 R18.2 | length 1987.2
  Top Layer w6: R18.2@1659.6,1372.4 1707.6,1372.4 v1(1710,1370)
  Mid-Layer 4 w6: v1@1209,13 1250,54 1310,54 1736,480 1736,644.46 1715.46,665 1715,665 1658,722 1658,785 1569,874 1569,1013 1656.64,1100.64 1656.64,1139.64 1692,1175 1692,1322 1710,1340 v1(1710,1370)
  Bottom Layer w6: EC1.64@1148.42,-150.67 1152,-147.09 1152,-57.54 1162.54,-47 1173.46,-47 1190,-30.46 1190,-5 v1(1210,15)
HSEC_PGA1_GND: EC1.13 R48.1 | length 1482.7
  Top Layer w6: EC1.13@235.04,-150.67 235.04,-54.96 253,-37 253,-11 264,0 289,0 v1@305,16 ; v1(790,895) 795,895 819,919 855,919 R48.1@881.6,892.4
  Top Layer w12: EC1.13@235,-150.63 EC1.13@235.04,-150.67
  Mid-Layer 8 w6: v1(305,15) 317,27 317,277.46 427.54,388 427.54,388.54 463,424 463,512.46 459,516.46 459,693 661,895 v1(790,895)
HSEC_PGA3_GND: EC1.16 R50.1 | length 1462
  Top Layer w6: v1(790,814) 794,814 824,844 855,844 R50.1@881.6,817.4
  Mid-Layer 8 w6: v1@270,-25 291,-4 316,-4 327,7 327,22.46 328,23.46 328,255 425,352 459,352 476,369 476,695.86 592.14,812 v1@791,812
  Bottom Layer w6: EC1.16@266.53,-150.67 266.53,-91.99 247,-72.46 247,-51 v1@272,-26
  other v1: 272,-22
HSEC_PGA5_GND: EC1.29 R51.1 | length 1506.8
  Top Layer w6: v1(485,-65) 487.01,-67.01 EC1.29@487.01,-150.67 ; v1(795,970) 820,945 855.2,945 877.6,967.4 R51.1@881.6,967.4
  Mid-Layer 8 w6: v1(485,-65) 497,-53 497,22.46 490,29.46 490,694 566,770 792,770 810,788 810,955 v1(795,970)
HSEC_PGA7_GND: EC1.10 R54.1 | length 1695.5
  Top Layer w6: v1(1430,425) 1433.1,428.1 R54.1@1433.1,475.9
  Mid-Layer 3 w6: v1@215,70 223,62 471,62 604,195 740,195 980,435 1076,435 1114,473 1382,473 v1(1430,425)
  Bottom Layer w6: EC1.10@172.05,-150.67 172.05,-92.41 203,-61.46 203,53 v1@215,65 ; v1@214,66 v1(215,67)
HSEC_PGA246_GND: EC1.19 EC1.22 EC1.35 R52.1 | length 1538.7
  Top Layer w6: EC1.19@329.53,-150.67 329.53,-80 344.53,-65 v1(345,-65) ; v1(580,-65) 581.49,-66.49 EC1.35@581.49,-150.67 ; v1(1261,412) 1263.1,414.1 R52.1@1263.1,475.9
  Mid-Layer 3 w6: v1@345,-64 v1(345,-65) 363,-47 563,-47 v1@579,-63 ; v1@345,-63 v1@345.5,-63.5 ; v1@581,-65 v1@579,-63 ; 756,117 793,154 793,228 980,415 1083,415 1114,446 1229,446 v1@1261,414 ; 757.5,115.5 v1@579,-63
  Bottom Layer w6: v1(345,-65) 361.02,-81.02 EC1.22@361.02,-150.67
HSEC_PIN58: EC1.58 S3.3 S3.4 | length 988.1
  Top Layer w6: v1@1119,-24 v1@1122.5,-20.5 ; v1(1120,-18) 1135,-3 1177.46,-3 1190,9.54 1190,44 1271,125 1530,125 1590,185 S3.4@1600,185 ; S3.4@1602.17,183.5 1658.5,183.5 1676,201 1676,306 1691.3,321.3 S3.3@1747.83,321.3
  Bottom Layer w6: EC1.58@1059.39,-122 1059.39,-69.11 1092,-36.5 1101.5,-36.5 v1(1120,-18)
HSEC_PIN60: EC1.60 S2.1 S2.6 | length 895
  Top Layer w6: v1@1125,16 1140,31 1156,31 1265,140 1460,140 1470.93,150.93 S2.6@1470.93,183.5 ; S2.1@1325.27,321.3 1383.7,321.3 1398,307 1398,217 1430,185 S2.6@1465,185 ; S2.6@1470.93,185 S2.6@1475,185
  Bottom Layer w6: EC1.60@1085.43,-150.67 1085.43,-65.57 1104.5,-46.5 1124.5,-46.5 1140,-31 1140,0 v1@1124,16
  other v1: 1124,15
HSEC_PIN75: EC1.75 S5.3 | length 1426.1
  Top Layer w6: 1336.9,-60.1 1348,-49 1348,44 1411,107 1759,107 1803,151 1803,346 1840,383 1903,383 1987,467 1987,467.46 1990,470.46 1990,660 1980,670 ; EC1.75@1337.4,-150.67 1337.4,-60.6 ; v1(1890,670) 1891.3,671.3 S5.3@1940.93,671.3 1980,671.3
HSEC_PIN77: EC1.77 S5.6 | length 1568.7
  Top Layer w6: EC1.77@1368.9,-150.67 1368.9,-58.1 1390.39,-36.61 1390.39,40.39 1442,92 1768,92 1820,144 1820,338 1850,368 1913,368 2005,460 2005,685 1975,715 ; S5.6@1795.27,671.3 1838,671.3 1838,673 1881,716 1975,716
HSEC_PIN79: EC1.79 S6.3 | length 750.2
  Top Layer w6: EC1.79@1400.39,-150.67 1400.39,32.39 1450,82 1822,82 1875,135 S6.3@1875,185
HSEC_PIN81: EC1.81 S6.6 | length 860.8
  Top Layer w6: EC1.81@1431.89,-150.67 1431.89,-16 ; 1432,-16 1446,-2 1446,27 1489,70 1965,70 2022.83,127.83 S6.6@2022.83,182.83 ; S6.6@2022.83,183.5 S6.6@2022.83,182.83 ; S6.6@2025,185 S6.6@2022.83,182.83
HSEC_PIN85: EC1.85 S2.3 S2.4 | length 677.6
  Top Layer w6: S2.3@1325.27,183.5 1378.5,183.5 1379,184 v1(1379,183) ; v1(1420,322.6) 1418.7,321.3 S2.4@1470.93,321.3 ; EC1.85@1494.88,-150.67 1494.88,-43.12 v1(1519,-19) v1@1520,-18
  Mid-Layer 7 w6: v1(1420,322.6) v1@1420,330
  Bottom Layer w6: v1@1377,184 1441.5,119.5 ; v1(1379,183) 1379,184 1398,203 1398,302 v1@1419,323 ; 1441,119 1519,41 v1(1519,-19)
HSEC_PIN87: EC1.87 S3.1 S3.6 | length 680.1
  Top Layer w6: EC1.87@1526.38,-150.67 1526.38,-57.62 1551,-33 v1@1551,-19 ; v1@1550,-19 v1(1550,-17) ; S3.6@1602.17,321.3 1651.3,321.3 v1(1655,325) ; v1(1691,179) 1742,179 S3.1@1747,184
  Bottom Layer w6: v1@1549,-17 1566.5,0.5 1580.5,0.5 1691,111 v1(1691,179) ; v1(1655,325) 1655,324 1676,303 1676,197 v1@1693,180
HSEC_PIN100: EC1.100 S5.1 | length 878.3
  Top Layer w6: v1(1890,535) 1891.5,533.5 S5.1@1940.93,533.5
  Bottom Layer w6: EC1.100@1715.35,-150.67 1715.35,-75.1 1718,-72.46 1718,116 1810,208 1810,542 1825,557 1869,557 v1@1890,536
HSEC_PIN102: EC1.102 S5.4 | length 785.2
  Top Layer w6: S5.4@1795.27,533.5 1848.5,533.5 v1(1849,533)
  Bottom Layer w6: EC1.102@1746.85,-150.67 1746.85,-88.61 1760,-75.46 1760,130 1769,139 ; 1766,135 1849,218 v1(1849,533)
HSEC_PIN107: EC1.107 S6.1 | length 561.9
  Top Layer w6: v1(1840,-65) 1841.34,-66.34 EC1.107@1841.34,-150.67 ; S6.1@1877.17,321.3 1929.7,321.3 v1(1930,321)
  Bottom Layer w6: v1(1840,-65) 1840,138 1905,203 1905,294 v1@1931,320
HSEC_PIN109: EC1.109 S6.4 | length 561.6
  Top Layer w6: EC1.109@1872.83,-150.67 1872,-149.84 1872,-35 v1(1890,-17) ; v1(1972,319) 1971.5,318.5 S6.4@2020.93,318.5
  Bottom Layer w6: v1(1890,-17) 1890,105 1951,166 1951,270 1972,291 v1(1972,319)
HSEC_TDI: EC1.8 R8.1 S4.3 U8:A.18 | length 3853.8
  Top Layer w6: S4.3@1020.27,183.5 1030.5,183.5 1069,145 v1@1069,119 ; v1(1610,1815) 1617.82,1822.82 U8:A.18@1662.34,1822.82
  Mid-Layer 3 w6: v1(175,-64) 184,-64 225,-105 825,-105 862,-68 862,10 857,15 857,55.6 915.4,114 1069,114 v1(1070,115)
  Mid-Layer 4 w6: v1(1070,115) 1090,95 1200,95 1310,205 1441,205 1726,490 1726,595.57 1648,673.57 1648,780.86 1559,869.86 1559,1019.86 1645,1105.86 1645,1144 1682,1181 1682,1380 1732,1430 1732,1628 1700,1660 1598,1660 1585,1673 1585,1790 v1(1610,1815)
  Bottom Layer w6: EC1.8@140.55,-150.67 140.55,-86.45 146.5,-80.5 159.5,-80.5 v1@176,-64 ; R8.1@1028.62,185 1028.62,149.38 1063,115 v1(1070,115)
HSEC_TDO: EC1.6 R9.1 S4.6 U8:A.8 | length 3882.1
  Top Layer w6: v1(1115,115) 1115,145 1153.5,183.5 S4.6@1165.93,183.5 ; U8:A.8@1430.05,1694.87 1464.87,1694.87 v1(1480,1710)
  Mid-Layer 3 w6: v1@85,-60 v1(90,-60) 135,-105 210.86,-105 220.86,-115 830,-115 872,-73 872,31.54 867,36.54 867,51.46 877.54,62 878.14,62 916.14,100 1020,100 1025,95 1095,95 v1(1115,115) ; v1@1113,117 v1@1117,121
  Mid-Layer 4 w6: v1(1115,115) 1129.5,129.5 1129.5,145.5 1199,215 1429,215 1709,495 1709,598.43 1638,669.43 1638,776.72 1549,865.72 1549,1024 1631,1106 1631,1146 1672,1187 1672,1386 1720,1434 1720,1618 1694,1644 1545,1644 1528,1661 ; v1(1480,1710) 1528.5,1661.5
  Bottom Layer w6: v1(90,-60) 109.05,-79.05 EC1.6@109.05,-150.67 ; v1(1115,115) 1115,148 1152,185 1154,185 1155,186 R9.1@1157,184 ; R9.1@1156.38,188.78 R9.1@1158.1,188.78
MCU_1V2: C1.1 C2.1 C3.2 C4.2 C5.2 C6.2 R22.1 TP3.1 U1.4 U1.46 U1.71 U1.87 | length 699.9
  Top Layer w12: v1(1021,1171) 1021,1155 1034.27,1141.73 U1.4@1073.97,1141.73 ; v1(1240,1362) 1279.2,1362 R22.1@1286.1,1368.9 ; R22.1@1285,1370 R22.1@1286.1,1368.9 ; U1.87@1397.79,1268.7 1397.79,1312.21 1390,1320 v1(1385,1320) 1385,1340 1354.1,1370.9 R22.1@1288.1,1370.9 R22.1@1286.1,1368.9 ; U1.46@1535.58,660.43 1535.58,708.58 1568,741 v1(1581,741) ; U1.71@1682.23,1122.04 1731.04,1122.04 1728.08,1125 v1(1725,1125) ; v1@1773,1119 v1@1776,1122
  Bottom Layer w12: v1@1020,1172 v1(1021,1171) 1023.38,1168.62 C6.2@1070,1168.62 ; C1.1@1366.6,1357.4 1366.6,1333.4 1375,1325 ; 1388.1,1156.02 1417.02,1156.02 v1(1420,1153) ; C5.2@1533.62,765 1533.62,781.62 1558,806 v1(1558,805) ; v1@1773,1119 v1@1776,1122 ; v1@1782.62,1119 C4.2@1810,1146.38
  other v1: 1774,1122
MCU_3V3: C8.1 C14.1 C15.1 C16.1 C17.1 L1.2 U1.3 U1.47 U1.70 U1.88 | length 708
  Top Layer w12: U1.3@1073.97,1161.41 1124.59,1161.41 1152,1134 1190,1134 v1(1191,1135) ; v1@1336,1190 1378.1,1232.1 U1.88@1378.1,1268.7 ; v1@1529,546 v1(1530,545) 1550,525 L1.2@1595,525 ; U1.47@1555.27,660.43 1555.27,614.73 1563,607 v1(1565,607) ; v1@1599.64,1102.36 U1.70@1682.23,1102.36
  Bottom Layer w12: v1@1186.38,1135 v1(1191,1135) ; v1@1190,1136 v1(1191,1135) ; C14.1@1201.38,1092 1201.38,1124.62 v1(1191,1135) ; v1(1336,1189) 1336,1205 C17.1@1362,1231 ; v1@1528,545 1529.1,543.9 C8.1@1583.1,543.9 ; C15.1@1564.52,649.99 1564.52,607.48 v1(1565,607) ; v1@1590,1102 1595.62,1096.38 C16.1@1650,1096.38
  other v1: 1530,515 1592,1102
MCU_A_3V3: C11.2 C12.2 C13.2 C32.1 C33.1 L2.2 U1.11 U1.34 U5.5 U6.5 U7.5 U8.5 U9.5 | length 761.8
  Top Layer w12: U5.5@-26.9,546.53 -26.9,511.1 -23,507.2 v1(-23,506) ; v1@106,515 109.62,518.62 C32.1@150,518.62 ; U9.5@273.1,546.53 273.1,516.9 v1(287,503) ; C33.1@400,503.62 443.62,503.62 v1(445,505) ; L2.2@925,1045 981,1045 v1@986,1050 ; U1.11@1073.97,1003.93 1133.07,1003.93 v1@1155,982 ; v1(1265,740) 1265,735 1299.36,700.64 U1.34@1299.36,660.43
  Bottom Layer w12: U6.5@-26.9,438.27 -26.9,467.2 -28,468.3 -28,506 v1@-25,509 ; U7.5@273.1,546.53 273.1,516.9 v1(287,503) ; U8.5@593.97,172.4 633.4,172.4 v1@636,175 ; C11.2@936.5,1050 985,1050 v1@985,1055 ; v1(1155,980) 1178.5,956.5 C12.2@1178.5,930 ; v1@1155,981 v1@1155.5,980.5 ; v1(1265,740) 1273.5,748.5 C13.2@1315,748.5
  other v1: 635,175 105,515 986,1026 985,1056
MCU_ADC-A0: C48.1 R36.1 U1.23 | length 1452
  Top Layer w6: C48.1@-141.9,305.9 R36.1@-66.9,305.9 -66.9,304.9 v1@-17,255 ; v1(985,740) 1005,760 1030,760 1037,767 1073.25,767 U1.23@1073.97,767.71
  Mid-Layer 3 w6: v1@-16,255 57,328 142,328 257,443 291.86,443 518.86,670 887,670 957,740 v1(985,740) ; v1@-15.5,253.5 v1@-14,252 ; v1(-15,254) v1@-15,255
MCU_ADC-A1: C49.1 R38.1 U1.22 | length 1362.3
  Top Layer w6: R38.1@13.1,305.9 C49.1@87.9,305.9 ; C49.1@88.1,305.9 126,268 142,252 v1(160,252) ; v1@1027.4,787.4 U1.22@1073.97,787.4
  Mid-Layer 3 w6: v1@161,252 171.5,262.5 171.5,331.5 268,428 291,428 349,486 349.7,486 465,601.3 465,602 523,660 936,660 1006,730 1006,766 v1(1024,784) v1@1025,785
MCU_ADC-A3: C50.1 R41.1 U1.10 | length 1428.1
  Top Layer w6: R41.1@13.1,683.9 89.9,683.89 C50.1@88.1,683.9 ; C50.1@85,685 85,690 v1@130,735 ; U1.10@1073.97,1023.62 1147.38,1023.62 v1@1158,1013
  Mid-Layer 3 w6: v1(125,735) 145,715 250,715 260,725 260,745 270,755 827,755 943,871 943,902 972,931 1071,931 v1(1155,1015)
MCU_ADC-A5: C51.1 R44.1 U1.35 | length 1716.7
  Top Layer w6: C51.1@-136.9,683.9 R44.1@-63.1,683.9 ; R44.1@-61.9,683.9 -61.9,713.1 v1(-40,735) ; v1(1265,770) 1319.04,715.96 U1.35@1319.04,660.43
  Mid-Layer 3 w6: v1(-40,735) -40,675 -17,652 462.14,652 490.14,680 827,680 950,803 1204,803 1227,780 1255,780 v1(1265,770)
MCU_ADC-A9: C52.1 R47.1 U1.38 | length 1432.3
  Top Layer w6: v1(1375,605) 1378.1,608.1 U1.38@1378.1,660.43
  Mid-Layer 3 w6: v1(389,256) 389,349.46 554.54,515 1010,515 1135,640 1245,640 1260,625 1260,600 1262,598 1262,597.54 ; 1259.77,599.77 1262,597.54 ; v1(1375,605) 1357,587 1272.54,587 1262,597.54
  Bottom Layer w6: R47.1@313.1,305.9 C52.1@391.1,305.9 ; C52.1@388.1,305.9 388.1,256.9 v1(389,256)
MCU_ADC-B0: C53.1 R49.1 U1.41 | length 1669.5
  Top Layer w6: 1437.16,617.16 U1.41@1437.16,660.43
  Mid-Layer 3 w6: v1@240,256 v1(240,255) 240,240 253,227 396,227 408,239 408,260 473,325 530,325 565,360 565,455 610,500 1009.14,500 1137.14,628 1237,628 1245,620 1245,600 1268,577 1407,577 v1(1435,605)
  Bottom Layer w6: C53.1@163.1,305.9 R49.1@238.1,305.9 240,304 v1(240,255) 240,254 v1@239,253
  Bottom Layer w12: R49.1@238.1,305.9 239.1,305.9 R49.1@240,305
MCU_ADC-B3: C54.1 R53.1 U1.8 | length 1308.1
  Top Layer w6: U1.8@1073.97,1062.99 1117.99,1062.99 1135.97,1045 v1(1163,1045)
  Mid-Layer 3 w6: v1(240,735) 240,760 245,765 816,765 924,873 924,905 961,942 1047,942 1150,1045 v1(1163,1045)
  Bottom Layer w6: C54.1@163.1,683.9 237.9,683.9 240,686 v1(240,735)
